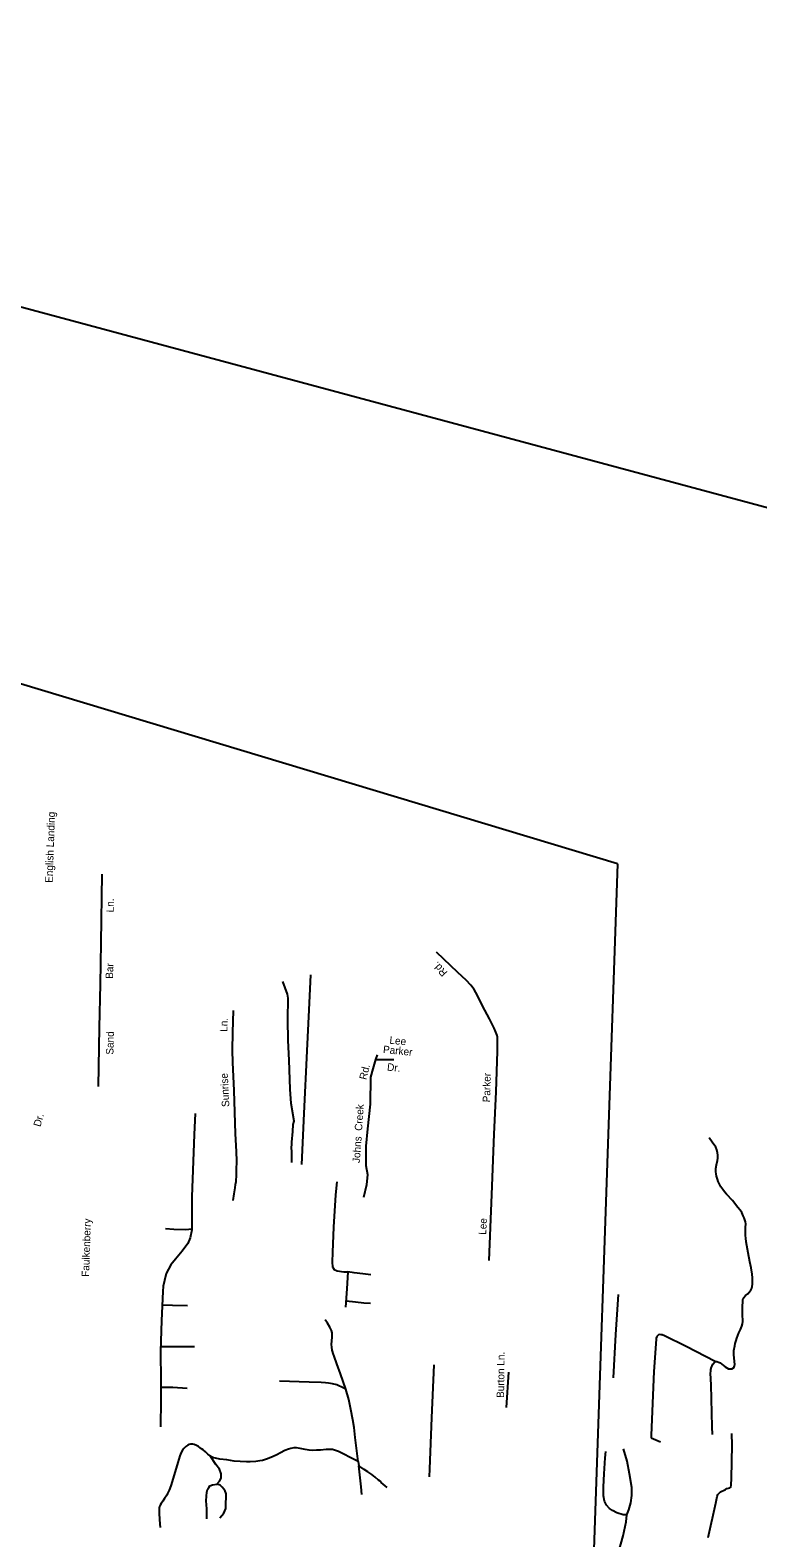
# Model space of a CAD drawing. Extents: x 2308163 to 2335412, y -96774 to 125428.
# Drawn here: x 2321460.1 to 2321659.7, y 52737.2 to 53151 of the extents above; entities that cross this region are included whole.
import ezdxf

# ---------------------------------------------------------------- set-up
doc = ezdxf.new("R2010")
doc.units = 0
for name, color, linetype in [('Old_Level_10', 7, 'Continuous'), ('Old_Level_35', 7, 'Continuous'), ('Old_Level_63', 7, 'Continuous')]:
    doc.layers.add(name, color=color, linetype=linetype)

msp = doc.modelspace()

# ---------------------------------------------------------------- linework, layer by layer
at = {"layer": 'Old_Level_35'}
for p, q in [((2321630.51, 52765.33), (2321630.48, 52764.62)), ((2321630.48, 52764.62), (2321633.08, 52763.56)), ((2321647.27, 52765.51), (2321647.21, 52767.64)), ((2321550.09, 52758.12), (2321550.25, 52756.93)), ((2321550.9, 52751.2), (2321550.25, 52756.93)), ((2321569.68, 52753.92), (2321569.77, 52756.09)), ((2321551.14, 52749.08), (2321550.9, 52751.2)), ((2321495.64, 52742.14), (2321495.76, 52740.03))]:
    msp.add_line(p, q, dxfattribs=at)
for points in [[(2321478.92, 52861.01), (2321479.19, 52877.25), (2321479.42, 52889.13), (2321479.63, 52900.5), (2321479.89, 52919.32)], [(2321586.02, 52813.34), (2321586.76, 52831.38), (2321587.41, 52847.94), (2321587.95, 52859.62), (2321588.34, 52870.74), (2321588.34, 52871.65), (2321588.34, 52872.77), (2321588.35, 52873.86), (2321588.31, 52874.61), (2321588.2, 52875.06), (2321587.91, 52875.94), (2321587.43, 52877.02), (2321586.11, 52879.67), (2321584.86, 52882.01), (2321582.41, 52886.89), (2321581.96, 52887.72), (2321581.03, 52888.86), (2321579.69, 52890.27), (2321577.48, 52892.33), (2321571.55, 52897.9)], [(2321531.88, 52840.21), (2321531.89, 52843.16), (2321531.86, 52844.34), (2321531.94, 52845.09), (2321531.95, 52845.79), (2321532.21, 52848.71), (2321532.32, 52850.58), (2321532.53, 52851.58), (2321531.77, 52856.41), (2321531.49, 52860.36), (2321531.19, 52868.31), (2321530.88, 52873.69), (2321530.77, 52879.45), (2321530.91, 52885.32), (2321530.69, 52886.4), (2321529.46, 52889.85)], [(2321534.61, 52839.66), (2321535.29, 52853.62), (2321536.14, 52870.85), (2321536.66, 52882.09), (2321537.08, 52891.71)], [(2321516.5, 52848.02), (2321516.1, 52859.97), (2321515.72, 52867.62), (2321515.61, 52871), (2321515.73, 52875.87), (2321515.94, 52881.94)], [(2321555.31, 52869.78), (2321554.87, 52868.45), (2321554.15, 52865.94), (2321553.51, 52863.58), (2321553.42, 52856.21), (2321552.71, 52849.42), (2321552.23, 52844.68), (2321552.2, 52839.37), (2321552.67, 52836.9), (2321552.41, 52834.05), (2321551.53, 52830.55)], [(2321554.87, 52868.45), (2321559.88, 52868.44)], [(2321505.38, 52853.65), (2321505.09, 52847.84), (2321504.5, 52830.76), (2321504.45, 52823.99), (2321504.45, 52821.76), (2321504.04, 52819.48), (2321503.35, 52817.97), (2321501.85, 52815.88), (2321499.99, 52813.63), (2321498.69, 52812.07), (2321497.47, 52809.76), (2321496.94, 52807.85), (2321496.58, 52806.29), (2321496.53, 52804.76), (2321496.15, 52796.79), (2321495.91, 52788.29), (2321495.99, 52780.27), (2321495.98, 52774.93), (2321495.91, 52767.62)], [(2321515.81, 52829.79), (2321516.1, 52831.59), (2321516.4, 52833.22), (2321516.48, 52834.15), (2321516.63, 52834.96), (2321516.73, 52836.83), (2321516.76, 52838.15), (2321516.83, 52840.57), (2321516.76, 52843.21), (2321516.5, 52848.02)], [(2321648.05, 52785.57), (2321648.24, 52785.57), (2321648.5, 52785.57), (2321648.93, 52785.43), (2321649.48, 52785.17), (2321649.85, 52784.84), (2321650.78, 52784.14), (2321651.26, 52783.8), (2321651.67, 52783.6), (2321652.18, 52783.54), (2321652.64, 52783.59), (2321653.03, 52783.83), (2321653.21, 52784.07), (2321653.34, 52784.4), (2321653.42, 52784.76), (2321653.16, 52787.39), (2321653.18, 52788.08), (2321653.2, 52788.58), (2321653.42, 52789.88), (2321653.56, 52790.51), (2321653.77, 52791.38), (2321653.97, 52792), (2321654.23, 52792.68), (2321654.57, 52793.49), (2321654.94, 52794.34), (2321655.36, 52795.28), (2321655.57, 52795.96), (2321655.64, 52796.52), (2321655.59, 52797.03), (2321655.56, 52798.09), (2321655.52, 52799.22), (2321655.55, 52800.72), (2321655.59, 52801.97), (2321655.66, 52802.46), (2321655.71, 52802.86), (2321655.88, 52803.18), (2321656.38, 52803.69), (2321656.95, 52804.18), (2321657.4, 52804.61), (2321657.79, 52805.16), (2321658.06, 52805.68), (2321658.22, 52806.18), (2321658.27, 52806.84), (2321658.28, 52807.52), (2321658.24, 52808.53), (2321658.14, 52809.53), (2321657.88, 52811.28), (2321657.53, 52812.92), (2321657.1, 52815.43), (2321656.54, 52818.45), (2321656.41, 52819.4), (2321656.34, 52820.14), (2321656.31, 52821.08), (2321656.39, 52822.39), (2321656.42, 52823.33), (2321656.36, 52823.89), (2321656.19, 52824.45), (2321655.99, 52824.98), (2321655.72, 52825.6), (2321655.31, 52826.43), (2321654.88, 52827.11), (2321654.27, 52827.88), (2321652.82, 52829.73), (2321651.17, 52831.52), (2321650.62, 52832.15), (2321650.14, 52832.8), (2321649.6, 52833.55), (2321649.22, 52834.23), (2321648.87, 52834.98), (2321648.65, 52835.58), (2321648.42, 52836.4), (2321648.3, 52837.09), (2321648.26, 52837.59), (2321648.25, 52838.54), (2321648.36, 52839.53), (2321648.64, 52840.77), (2321648.76, 52841.39), (2321648.79, 52842.23), (2321648.69, 52842.83), (2321648.46, 52843.71), (2321648.23, 52844.41), (2321647.2, 52845.81), (2321646.36, 52847.01)], [(2321544.3, 52834.92), (2321543.91, 52831.35), (2321543.36, 52822.43), (2321543.04, 52815.61), (2321542.95, 52812.85), (2321543.07, 52811.55), (2321543.53, 52810.8), (2321544.33, 52810.45), (2321546.19, 52810.22), (2321547.25, 52810.19)], [(2321504.45, 52821.93), (2321502.8, 52821.71), (2321499.52, 52821.82), (2321497.23, 52822.01)], [(2321547.25, 52810.19), (2321547.01, 52805.56), (2321546.67, 52800.53)], [(2321553.56, 52809.32), (2321551.38, 52809.64), (2321549.03, 52809.88), (2321547.25, 52810.19)], [(2321496.35, 52801.1), (2321499.14, 52801.06), (2321503.29, 52800.92)], [(2321546.78, 52802.19), (2321549.41, 52801.98), (2321551.67, 52801.66), (2321553.46, 52801.6)], [(2321620.18, 52781.12), (2321620.79, 52792.99), (2321621.49, 52803.98)], [(2321546.75, 52777.95), (2321545.3, 52782.19), (2321544.24, 52784.9), (2321543.49, 52787.02), (2321543.21, 52787.81), (2321543.07, 52788.37), (2321542.97, 52788.67), (2321542.84, 52789.49), (2321542.81, 52790.25), (2321542.89, 52791.25), (2321542.97, 52792.24), (2321542.99, 52792.8), (2321542.93, 52793.41), (2321542.77, 52794.06), (2321542.35, 52795), (2321541.69, 52796.09), (2321541.09, 52796.98)], [(2321648.05, 52785.57), (2321640.09, 52789.7), (2321634.15, 52792.6), (2321633.54, 52792.87), (2321633.23, 52792.94), (2321632.87, 52792.97), (2321632.49, 52792.86), (2321632.22, 52792.65), (2321632.03, 52792.4), (2321631.88, 52791.99), (2321631.88, 52791.72), (2321631.23, 52782.85), (2321630.51, 52765.33)], [(2321495.95, 52789.66), (2321498.74, 52789.71), (2321505.2, 52789.7)], [(2321569.77, 52756.09), (2321570.33, 52770.08), (2321571, 52784.68)], [(2321647.21, 52767.64), (2321646.9, 52779.16), (2321646.79, 52782.36), (2321646.8, 52782.92), (2321646.84, 52783.38), (2321647.02, 52783.98), (2321647.2, 52784.41), (2321647.41, 52784.84), (2321648.05, 52785.57)], [(2321590.8, 52772.92), (2321591.43, 52782.61)], [(2321503.16, 52778.18), (2321499.23, 52778.43), (2321495.99, 52778.47)], [(2321546.75, 52777.95), (2321545.65, 52778.49), (2321544.84, 52778.88), (2321544.22, 52779.14), (2321543.04, 52779.49), (2321541.98, 52779.64), (2321541.11, 52779.72), (2321539.92, 52779.81), (2321536.67, 52779.89), (2321528.55, 52780.16)], [(2321550.09, 52758.12), (2321549.25, 52764.76), (2321549, 52767.47), (2321548.68, 52769.53), (2321548.13, 52772.42), (2321547.51, 52775.19), (2321546.75, 52777.95)], [(2321646.14, 52737.29), (2321648.24, 52746.74), (2321648.56, 52748.54), (2321648.8, 52749.11), (2321649.18, 52749.53), (2321649.51, 52749.78), (2321649.82, 52749.96), (2321650.32, 52750.19), (2321650.84, 52750.43), (2321651.21, 52750.68), (2321651.35, 52750.7), (2321651.71, 52750.77), (2321652.07, 52750.91), (2321652.31, 52751.1), (2321652.41, 52751.65), (2321652.55, 52753.57), (2321652.74, 52762.59), (2321652.58, 52765.86)], [(2321508.25, 52760.76), (2321507.59, 52761.3), (2321507.09, 52761.65), (2321506.78, 52761.92), (2321506.35, 52762.24), (2321505.79, 52762.53), (2321505.12, 52762.77), (2321504.73, 52762.88), (2321504.12, 52762.92), (2321503.75, 52762.8), (2321503.37, 52762.63), (2321502.86, 52762.26), (2321502.27, 52761.71), (2321501.95, 52761.28), (2321501.6, 52760.57), (2321501.23, 52759.68), (2321500.62, 52757.82), (2321499.12, 52752.67), (2321498.72, 52751.42), (2321498.29, 52750.3), (2321497.81, 52749.32), (2321497.59, 52748.89), (2321497.01, 52747.97), (2321496.49, 52747.22), (2321496.1, 52746.6), (2321495.77, 52746.17), (2321495.64, 52745.8), (2321495.5, 52745.31), (2321495.49, 52744.88), (2321495.54, 52744.06), (2321495.64, 52742.14)], [(2321550.09, 52758.12), (2321548.12, 52759.17), (2321546.01, 52760.28), (2321544.72, 52760.88), (2321543.66, 52761.28), (2321543.05, 52761.42), (2321542.3, 52761.43), (2321541.35, 52761.39), (2321539.79, 52761.24), (2321538.66, 52761.2), (2321537.59, 52761.17), (2321536.66, 52761.26), (2321535.54, 52761.42), (2321534.23, 52761.7), (2321533.17, 52761.84), (2321532.42, 52761.86), (2321531.67, 52761.69), (2321531.04, 52761.52), (2321529.97, 52761.11), (2321528.82, 52760.51), (2321527.81, 52759.97), (2321526.8, 52759.5), (2321525.73, 52759.02), (2321524.97, 52758.73), (2321523.9, 52758.45), (2321523.15, 52758.33), (2321522.08, 52758.17), (2321520.5, 52758.07), (2321519.48, 52758.06), (2321517.71, 52758.12), (2321516.08, 52758.25), (2321514.08, 52758.55), (2321512.15, 52758.79), (2321510.97, 52759.01), (2321510.44, 52759.18), (2321509.91, 52759.4), (2321509.48, 52759.67), (2321508.87, 52760.11), (2321508.25, 52760.76)], [(2321512.18, 52742.65), (2321513.28, 52743.91), (2321513.78, 52745.22), (2321513.84, 52746.91), (2321513.91, 52748.08), (2321513.93, 52748.71), (2321513.92, 52749.23), (2321513.83, 52749.55), (2321513.61, 52750.01), (2321513.26, 52750.55), (2321512.78, 52751.12), (2321512.22, 52751.66), (2321511.3, 52751.91), (2321512.05, 52752.71), (2321512.55, 52753.6), (2321512.56, 52754.74), (2321512.1, 52756.07), (2321511.1, 52757.28), (2321509.48, 52759.67)], [(2321623.84, 52743.45), (2321622.78, 52743.48), (2321621.02, 52744.02), (2321619.86, 52744.65), (2321619.06, 52745.26), (2321618.26, 52746.12), (2321617.71, 52747.2), (2321617.41, 52748.74), (2321617.37, 52751.22), (2321617.61, 52754.76), (2321617.88, 52759.11), (2321618.08, 52760.89)], [(2321623.84, 52743.45), (2321624.36, 52744.85), (2321624.9, 52746.83), (2321625.2, 52748.83), (2321625.16, 52750.95), (2321624.58, 52754.75), (2321623.87, 52758.2), (2321622.9, 52761.61)], [(2321556.13, 52752.69), (2321555.72, 52753.05), (2321554.79, 52753.84), (2321553.88, 52754.53), (2321552.77, 52755.31), (2321551.73, 52755.96), (2321550.25, 52756.93)], [(2321508.58, 52742.38), (2321508.62, 52745.17), (2321508.44, 52747.33), (2321508.46, 52748.65), (2321508.56, 52749.72), (2321508.75, 52750.42), (2321509.11, 52751.04), (2321509.44, 52751.49), (2321510.14, 52751.76), (2321511.3, 52751.91)], [(2321558.09, 52751.04), (2321556.46, 52752.4), (2321556.13, 52752.69)], [(2321620.88, 52729.51), (2321621.34, 52732.56), (2321622.81, 52737.7), (2321623.65, 52741.57), (2321623.84, 52743.45)]]:
    msp.add_lwpolyline(points, dxfattribs=at)
at = {"layer": 'Old_Level_63'}
msp.add_line((2321621.26, 52922.18), (2321367.22, 52998.81), dxfattribs=at)
for points in [[(2322020.02, 52911.6), (2321937.45, 52945.83), (2321174.98, 53150.98)], [(2321621.26, 52922.18), (2321607.1, 52511.43), (2321350.69, 52519.52), (2321367.22, 52998.81)]]:
    msp.add_lwpolyline(points, dxfattribs=at)

# ---------------------------------------------------------------- texts
at = {"layer": 'Old_Level_10'}
for s, height, rotation, p in [('English Landing', 2.0505, 88.0247, (2321466.29, 52916.93)), ('Ln.', 2.051, 89.0989, (2321483.05, 52908.84)), ('Bar', 2.051, 88.1197, (2321482.85, 52890.59)), ('Rd.', 2.051, 132.9634, (2321574.73, 52892.4)), ('Sand', 2.051, 88.9158, (2321482.97, 52869.78)), ('Ln.', 2.051, 88.0624, (2321514.2, 52876.05)), ('Parker', 2.051, 354.2925, (2321556.85, 52870.26)), ('Lee', 2.051, 354.2925, (2321558.62, 52872.81)), ('Dr.', 2.051, 354.2925, (2321557.96, 52865.43)), ('Sunrise', 2.051, 92.8193, (2321514.78, 52855.49)), ('Rd.', 2.051, 76.1913, (2321552.35, 52862.76)), ('Parker', 2.051, 88.7193, (2321586.3, 52856.7)), ('Johns  Creek ', 2.0505, 86.0484, (2321550.56, 52840.01)), ('Dr.', 2.051, 74.2787, (2321462.95, 52849.85)), ('Faulkenberry', 2.0505, 88.1377, (2321476.29, 52808.8)), ('Lee', 2.051, 86.8925, (2321585.2, 52820.31)), ('Burton Ln.', 2.051, 89.2977, (2321590.12, 52775.57))]:
    msp.add_text(s, height=height, rotation=rotation, dxfattribs=at).set_placement(p)

doc.saveas('drawing.dxf')
